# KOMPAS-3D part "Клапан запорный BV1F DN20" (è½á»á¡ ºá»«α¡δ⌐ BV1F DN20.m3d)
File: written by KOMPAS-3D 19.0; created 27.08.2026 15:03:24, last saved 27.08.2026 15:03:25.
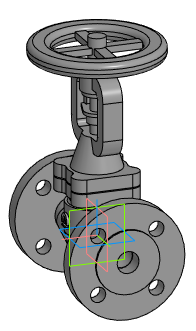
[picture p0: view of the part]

Document properties: Автор: Энергия; Полное имя файла: E:\Dendor\_3D для проектировщиков\5.6 Клапан запорный BV1F\stp\Клапан запорный BV1F DN20.m3d

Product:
- Part/product: Клапан запорный BV1F DN20
    Масса: 5.06789

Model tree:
1. Операция без истории:1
